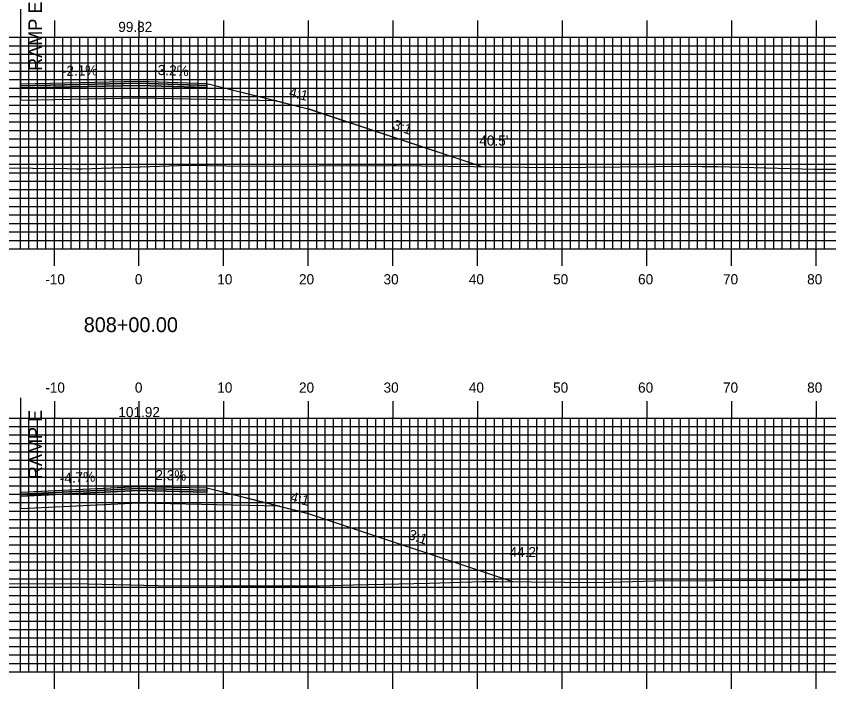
# Model space of a CAD drawing. Extents: x 1272 to 1616, y -1658 to -1438.
# Drawn here: x 1423.7 to 1519.7, y -1591.6 to -1512.1 of the extents above; entities that cross this region are included whole.
import ezdxf

# ---------------------------------------------------------------- set-up
doc = ezdxf.new("R2010")
doc.units = 0
for name, color, linetype in [('ANNOTATION', 7, 'Continuous'), ('D_Roadway_Centerline', 7, 'Continuous'), ('D_Roadway_Centerline_Text', 7, 'Continuous'), ('D_Roadway_Edge_Shoulder', 7, 'Continuous'), ('D_Roadway_Edge_TW', 7, 'Continuous'), ('D_Roadway_Pavement', 7, 'Continuous'), ('D_Roadway_SlopeLines', 7, 'Continuous'), ('D_Roadway_SubGrade', 7, 'Continuous'), ('D_Text_Standard', 7, 'Continuous'), ('H_V ANNOTATION', 7, 'Continuous'), ('MAJOR', 7, 'Continuous'), ('MINOR', 7, 'Continuous'), ('S_Roadway_Centerline', 7, 'Continuous')]:
    doc.layers.add(name, color=color, linetype=linetype)

msp = doc.modelspace()

# ---------------------------------------------------------------- linework, layer by layer
at = {"layer": 'D_Roadway_Centerline'}
for points in [[(1424.161, -1520.082), (1438.161, -1519.784), (1438.184, -1519.784), (1446.161, -1520.043), (1446.184, -1520.049), (1454.425, -1522.109), (1454.436, -1522.112), (1458.161, -1523.043), (1458.218, -1523.062), (1478.655, -1529.874)], [(1424.161, -1568.35), (1438.028, -1567.696), (1438.161, -1567.689), (1446.086, -1567.873), (1446.161, -1567.874), (1454.667, -1570.001), (1454.747, -1570.021), (1458.129, -1570.867), (1458.161, -1570.874), (1482.16, -1578.874), (1482.394, -1578.952)]]:
    msp.add_lwpolyline(points, dxfattribs=at)
at = {"layer": 'D_Roadway_Edge_Shoulder'}
for points in [[(1438.161, -1519.784), (1446.161, -1520.043), (1446.161, -1520.293), (1438.161, -1520.034)], [(1438.161, -1567.689), (1446.161, -1567.874), (1446.161, -1568.124), (1438.161, -1567.939)]]:
    msp.add_lwpolyline(points, close=True, dxfattribs=at)
at = {"layer": 'D_Roadway_Edge_TW'}
for points in [[(1424.161, -1520.082), (1438.161, -1519.784), (1438.161, -1520.034), (1424.161, -1520.332)], [(1424.161, -1568.35), (1438.161, -1567.689), (1438.161, -1567.939), (1424.161, -1568.6)]]:
    msp.add_lwpolyline(points, close=True, dxfattribs=at)
at = {"layer": 'D_Roadway_Pavement'}
for points in [[(1424.161, -1520.332), (1438.161, -1520.034), (1438.161, -1520.284), (1424.161, -1520.582)], [(1438.161, -1520.034), (1446.161, -1520.293), (1446.161, -1520.543), (1438.161, -1520.284)], [(1424.161, -1568.6), (1438.161, -1567.939), (1438.161, -1568.189), (1424.161, -1568.85)], [(1438.161, -1567.939), (1446.161, -1568.124), (1446.161, -1568.374), (1438.161, -1568.189)]]:
    msp.add_lwpolyline(points, close=True, dxfattribs=at)
for points in [[(1438.161, -1520.034), (1438.161, -1520.284)], [(1438.161, -1520.034), (1438.161, -1520.284)], [(1438.161, -1520.034), (1438.161, -1520.284)], [(1438.161, -1567.939), (1438.161, -1568.189)], [(1438.161, -1567.939), (1438.161, -1568.189)], [(1438.161, -1567.939), (1438.161, -1568.189)]]:
    msp.add_lwpolyline(points, dxfattribs=at)
at = {"layer": 'D_Roadway_SlopeLines'}
for points in [[(1446.161, -1520.043), (1458.161, -1523.043), (1478.655, -1529.874)], [(1446.161, -1567.874), (1458.161, -1570.874), (1482.394, -1578.952)], [(1446.161, -1567.874), (1458.161, -1570.874), (1482.394, -1578.952)]]:
    msp.add_lwpolyline(points, dxfattribs=at)
at = {"layer": 'D_Roadway_SubGrade'}
for p, q in [((1424.161, -1508.942), (1424.161, -1522.082)), ((1424.161, -1557.21), (1424.161, -1570.35))]:
    msp.add_line(p, q, dxfattribs=at)
for points in [[(1424.161, -1520.582), (1438.161, -1520.284), (1438.161, -1521.784), (1424.161, -1522.082)], [(1438.161, -1520.284), (1438.161, -1520.034), (1446.161, -1520.293), (1446.161, -1520.043), (1454.425, -1522.109), (1438.161, -1521.784)], [(1438.161, -1520.284), (1446.161, -1520.543), (1446.161, -1520.293), (1446.161, -1520.043), (1454.425, -1522.109), (1438.161, -1521.784)], [(1424.161, -1568.85), (1438.161, -1568.189), (1438.161, -1569.689), (1424.161, -1570.35)], [(1438.161, -1568.189), (1438.161, -1567.939), (1446.161, -1568.124), (1446.161, -1567.874), (1454.747, -1570.021), (1438.161, -1569.689)], [(1438.161, -1568.189), (1446.161, -1568.374), (1446.161, -1568.124), (1446.161, -1567.874), (1454.747, -1570.021), (1438.161, -1569.689)]]:
    msp.add_lwpolyline(points, close=True, dxfattribs=at)
at = {"layer": 'MAJOR'}
for p, q in [((1428.161, -1512.6), (1428.161, -1514.604)), ((1438.161, -1512.6), (1438.161, -1514.604)), ((1448.161, -1512.6), (1448.161, -1514.604)), ((1458.161, -1512.6), (1458.161, -1514.604)), ((1468.161, -1512.6), (1468.161, -1514.604)), ((1478.161, -1512.6), (1478.161, -1514.604)), ((1488.161, -1512.6), (1488.161, -1514.604)), ((1498.161, -1512.6), (1498.161, -1514.604)), ((1508.161, -1512.6), (1508.161, -1514.604)), ((1518.161, -1512.6), (1518.161, -1514.604)), ((1298.161, -1514.604), (1578.161, -1514.604)), ((1298.161, -1514.604), (1578.161, -1514.604)), ((1428.161, -1539.604), (1428.161, -1514.604)), ((1438.161, -1539.604), (1438.161, -1514.604)), ((1448.161, -1539.604), (1448.161, -1514.604)), ((1458.161, -1539.604), (1458.161, -1514.604)), ((1468.161, -1539.604), (1468.161, -1514.604)), ((1478.161, -1539.604), (1478.161, -1514.604)), ((1488.161, -1539.604), (1488.161, -1514.604)), ((1498.161, -1539.604), (1498.161, -1514.604)), ((1508.161, -1539.604), (1508.161, -1514.604)), ((1518.161, -1539.604), (1518.161, -1514.604)), ((1298.161, -1519.604), (1578.161, -1519.604)), ((1298.161, -1524.604), (1578.161, -1524.604)), ((1298.161, -1529.604), (1578.161, -1529.604)), ((1298.161, -1534.604), (1578.161, -1534.604)), ((1298.161, -1539.604), (1578.161, -1539.604)), ((1298.161, -1539.604), (1578.161, -1539.604)), ((1428.161, -1541.608), (1428.161, -1539.604)), ((1438.161, -1541.608), (1438.161, -1539.604)), ((1448.161, -1541.608), (1448.161, -1539.604)), ((1458.161, -1541.608), (1458.161, -1539.604)), ((1468.161, -1541.608), (1468.161, -1539.604)), ((1478.161, -1541.608), (1478.161, -1539.604)), ((1488.161, -1541.608), (1488.161, -1539.604)), ((1498.161, -1541.608), (1498.161, -1539.604)), ((1508.161, -1541.608), (1508.161, -1539.604)), ((1518.161, -1541.608), (1518.161, -1539.604)), ((1428.161, -1557.6), (1428.161, -1559.604)), ((1438.161, -1557.6), (1438.161, -1559.604)), ((1448.161, -1557.6), (1448.161, -1559.604)), ((1458.161, -1557.6), (1458.161, -1559.604)), ((1468.161, -1557.6), (1468.161, -1559.604)), ((1478.161, -1557.6), (1478.161, -1559.604)), ((1488.161, -1557.6), (1488.161, -1559.604)), ((1498.161, -1557.6), (1498.161, -1559.604)), ((1508.161, -1557.6), (1508.161, -1559.604)), ((1518.161, -1557.6), (1518.161, -1559.604)), ((1298.161, -1559.604), (1578.161, -1559.604)), ((1298.161, -1559.604), (1578.161, -1559.604)), ((1428.161, -1589.604), (1428.161, -1559.604)), ((1438.161, -1589.604), (1438.161, -1559.604)), ((1448.161, -1589.604), (1448.161, -1559.604)), ((1458.161, -1589.604), (1458.161, -1559.604)), ((1468.161, -1589.604), (1468.161, -1559.604)), ((1478.161, -1589.604), (1478.161, -1559.604)), ((1488.161, -1589.604), (1488.161, -1559.604)), ((1498.161, -1589.604), (1498.161, -1559.604)), ((1508.161, -1589.604), (1508.161, -1559.604)), ((1518.161, -1589.604), (1518.161, -1559.604)), ((1298.161, -1564.604), (1578.161, -1564.604)), ((1298.161, -1569.604), (1578.161, -1569.604)), ((1298.161, -1574.604), (1578.161, -1574.604)), ((1298.161, -1579.604), (1578.161, -1579.604)), ((1298.161, -1584.604), (1578.161, -1584.604)), ((1298.161, -1589.604), (1578.161, -1589.604)), ((1298.161, -1589.604), (1578.161, -1589.604)), ((1428.161, -1591.608), (1428.161, -1589.604)), ((1438.161, -1591.608), (1438.161, -1589.604)), ((1448.161, -1591.608), (1448.161, -1589.604)), ((1458.161, -1591.608), (1458.161, -1589.604)), ((1468.161, -1591.608), (1468.161, -1589.604)), ((1478.161, -1591.608), (1478.161, -1589.604)), ((1488.161, -1591.608), (1488.161, -1589.604)), ((1498.161, -1591.608), (1498.161, -1589.604)), ((1508.161, -1591.608), (1508.161, -1589.604)), ((1518.161, -1591.608), (1518.161, -1589.604))]:
    msp.add_line(p, q, dxfattribs=at)
at = {"layer": 'MINOR'}
for p, q in [((1424.161, -1539.604), (1424.161, -1514.604)), ((1425.161, -1539.604), (1425.161, -1514.604)), ((1426.161, -1539.604), (1426.161, -1514.604)), ((1427.161, -1539.604), (1427.161, -1514.604)), ((1429.161, -1539.604), (1429.161, -1514.604)), ((1430.161, -1539.604), (1430.161, -1514.604)), ((1431.161, -1539.604), (1431.161, -1514.604)), ((1432.161, -1539.604), (1432.161, -1514.604)), ((1433.161, -1539.604), (1433.161, -1514.604)), ((1434.161, -1539.604), (1434.161, -1514.604)), ((1435.161, -1539.604), (1435.161, -1514.604)), ((1436.161, -1539.604), (1436.161, -1514.604)), ((1437.161, -1539.604), (1437.161, -1514.604)), ((1439.161, -1539.604), (1439.161, -1514.604)), ((1440.161, -1539.604), (1440.161, -1514.604)), ((1441.161, -1539.604), (1441.161, -1514.604)), ((1442.161, -1539.604), (1442.161, -1514.604)), ((1443.161, -1539.604), (1443.161, -1514.604)), ((1444.161, -1539.604), (1444.161, -1514.604)), ((1445.161, -1539.604), (1445.161, -1514.604)), ((1446.161, -1539.604), (1446.161, -1514.604)), ((1447.161, -1539.604), (1447.161, -1514.604)), ((1449.161, -1539.604), (1449.161, -1514.604)), ((1450.161, -1539.604), (1450.161, -1514.604)), ((1451.161, -1539.604), (1451.161, -1514.604)), ((1452.161, -1539.604), (1452.161, -1514.604)), ((1453.161, -1539.604), (1453.161, -1514.604)), ((1454.161, -1539.604), (1454.161, -1514.604)), ((1455.161, -1539.604), (1455.161, -1514.604)), ((1456.161, -1539.604), (1456.161, -1514.604)), ((1457.161, -1539.604), (1457.161, -1514.604)), ((1459.161, -1539.604), (1459.161, -1514.604)), ((1460.161, -1539.604), (1460.161, -1514.604)), ((1461.161, -1539.604), (1461.161, -1514.604)), ((1462.161, -1539.604), (1462.161, -1514.604)), ((1463.161, -1539.604), (1463.161, -1514.604)), ((1464.161, -1539.604), (1464.161, -1514.604)), ((1465.161, -1539.604), (1465.161, -1514.604)), ((1466.161, -1539.604), (1466.161, -1514.604)), ((1467.161, -1539.604), (1467.161, -1514.604)), ((1469.161, -1539.604), (1469.161, -1514.604)), ((1470.161, -1539.604), (1470.161, -1514.604)), ((1471.161, -1539.604), (1471.161, -1514.604)), ((1472.161, -1539.604), (1472.161, -1514.604)), ((1473.161, -1539.604), (1473.161, -1514.604)), ((1474.161, -1539.604), (1474.161, -1514.604)), ((1475.161, -1539.604), (1475.161, -1514.604)), ((1476.161, -1539.604), (1476.161, -1514.604)), ((1477.161, -1539.604), (1477.161, -1514.604)), ((1479.161, -1539.604), (1479.161, -1514.604)), ((1480.161, -1539.604), (1480.161, -1514.604)), ((1481.161, -1539.604), (1481.161, -1514.604)), ((1482.161, -1539.604), (1482.161, -1514.604)), ((1483.161, -1539.604), (1483.161, -1514.604)), ((1484.161, -1539.604), (1484.161, -1514.604)), ((1485.161, -1539.604), (1485.161, -1514.604)), ((1486.161, -1539.604), (1486.161, -1514.604)), ((1487.161, -1539.604), (1487.161, -1514.604)), ((1489.161, -1539.604), (1489.161, -1514.604)), ((1490.161, -1539.604), (1490.161, -1514.604)), ((1491.161, -1539.604), (1491.161, -1514.604)), ((1492.161, -1539.604), (1492.161, -1514.604)), ((1493.161, -1539.604), (1493.161, -1514.604)), ((1494.161, -1539.604), (1494.161, -1514.604)), ((1495.161, -1539.604), (1495.161, -1514.604)), ((1496.161, -1539.604), (1496.161, -1514.604)), ((1497.161, -1539.604), (1497.161, -1514.604)), ((1499.161, -1539.604), (1499.161, -1514.604)), ((1500.161, -1539.604), (1500.161, -1514.604)), ((1501.161, -1539.604), (1501.161, -1514.604)), ((1502.161, -1539.604), (1502.161, -1514.604)), ((1503.161, -1539.604), (1503.161, -1514.604)), ((1504.161, -1539.604), (1504.161, -1514.604)), ((1505.161, -1539.604), (1505.161, -1514.604)), ((1506.161, -1539.604), (1506.161, -1514.604)), ((1507.161, -1539.604), (1507.161, -1514.604)), ((1509.161, -1539.604), (1509.161, -1514.604)), ((1510.161, -1539.604), (1510.161, -1514.604)), ((1511.161, -1539.604), (1511.161, -1514.604)), ((1512.161, -1539.604), (1512.161, -1514.604)), ((1513.161, -1539.604), (1513.161, -1514.604)), ((1514.161, -1539.604), (1514.161, -1514.604)), ((1515.161, -1539.604), (1515.161, -1514.604)), ((1516.161, -1539.604), (1516.161, -1514.604)), ((1517.161, -1539.604), (1517.161, -1514.604)), ((1519.161, -1539.604), (1519.161, -1514.604)), ((1298.161, -1515.604), (1578.161, -1515.604)), ((1298.161, -1516.604), (1578.161, -1516.604)), ((1298.161, -1517.604), (1578.161, -1517.604)), ((1298.161, -1518.604), (1578.161, -1518.604)), ((1298.161, -1520.604), (1578.161, -1520.604)), ((1298.161, -1521.604), (1578.161, -1521.604)), ((1298.161, -1522.604), (1578.161, -1522.604)), ((1298.161, -1523.604), (1578.161, -1523.604)), ((1298.161, -1525.604), (1578.161, -1525.604)), ((1298.161, -1526.604), (1578.161, -1526.604)), ((1298.161, -1527.604), (1578.161, -1527.604)), ((1298.161, -1528.604), (1578.161, -1528.604)), ((1298.161, -1530.604), (1578.161, -1530.604)), ((1298.161, -1531.604), (1578.161, -1531.604)), ((1298.161, -1532.604), (1578.161, -1532.604)), ((1298.161, -1533.604), (1578.161, -1533.604)), ((1298.161, -1535.604), (1578.161, -1535.604)), ((1298.161, -1536.604), (1578.161, -1536.604)), ((1298.161, -1537.604), (1578.161, -1537.604)), ((1298.161, -1538.604), (1578.161, -1538.604)), ((1424.161, -1589.604), (1424.161, -1559.604)), ((1425.161, -1589.604), (1425.161, -1559.604)), ((1426.161, -1589.604), (1426.161, -1559.604)), ((1427.161, -1589.604), (1427.161, -1559.604)), ((1429.161, -1589.604), (1429.161, -1559.604)), ((1430.161, -1589.604), (1430.161, -1559.604)), ((1431.161, -1589.604), (1431.161, -1559.604)), ((1432.161, -1589.604), (1432.161, -1559.604)), ((1433.161, -1589.604), (1433.161, -1559.604)), ((1434.161, -1589.604), (1434.161, -1559.604)), ((1435.161, -1589.604), (1435.161, -1559.604)), ((1436.161, -1589.604), (1436.161, -1559.604)), ((1437.161, -1589.604), (1437.161, -1559.604)), ((1439.161, -1589.604), (1439.161, -1559.604)), ((1440.161, -1589.604), (1440.161, -1559.604)), ((1441.161, -1589.604), (1441.161, -1559.604)), ((1442.161, -1589.604), (1442.161, -1559.604)), ((1443.161, -1589.604), (1443.161, -1559.604)), ((1444.161, -1589.604), (1444.161, -1559.604)), ((1445.161, -1589.604), (1445.161, -1559.604)), ((1446.161, -1589.604), (1446.161, -1559.604)), ((1447.161, -1589.604), (1447.161, -1559.604)), ((1449.161, -1589.604), (1449.161, -1559.604)), ((1450.161, -1589.604), (1450.161, -1559.604)), ((1451.161, -1589.604), (1451.161, -1559.604)), ((1452.161, -1589.604), (1452.161, -1559.604)), ((1453.161, -1589.604), (1453.161, -1559.604)), ((1454.161, -1589.604), (1454.161, -1559.604)), ((1455.161, -1589.604), (1455.161, -1559.604)), ((1456.161, -1589.604), (1456.161, -1559.604)), ((1457.161, -1589.604), (1457.161, -1559.604)), ((1459.161, -1589.604), (1459.161, -1559.604)), ((1460.161, -1589.604), (1460.161, -1559.604)), ((1461.161, -1589.604), (1461.161, -1559.604)), ((1462.161, -1589.604), (1462.161, -1559.604)), ((1463.161, -1589.604), (1463.161, -1559.604)), ((1464.161, -1589.604), (1464.161, -1559.604)), ((1465.161, -1589.604), (1465.161, -1559.604)), ((1466.161, -1589.604), (1466.161, -1559.604)), ((1467.161, -1589.604), (1467.161, -1559.604)), ((1469.161, -1589.604), (1469.161, -1559.604)), ((1470.161, -1589.604), (1470.161, -1559.604)), ((1471.161, -1589.604), (1471.161, -1559.604)), ((1472.161, -1589.604), (1472.161, -1559.604)), ((1473.161, -1589.604), (1473.161, -1559.604)), ((1474.161, -1589.604), (1474.161, -1559.604)), ((1475.161, -1589.604), (1475.161, -1559.604)), ((1476.161, -1589.604), (1476.161, -1559.604)), ((1477.161, -1589.604), (1477.161, -1559.604)), ((1479.161, -1589.604), (1479.161, -1559.604)), ((1480.161, -1589.604), (1480.161, -1559.604)), ((1481.161, -1589.604), (1481.161, -1559.604)), ((1482.161, -1589.604), (1482.161, -1559.604)), ((1483.161, -1589.604), (1483.161, -1559.604)), ((1484.161, -1589.604), (1484.161, -1559.604)), ((1485.161, -1589.604), (1485.161, -1559.604)), ((1486.161, -1589.604), (1486.161, -1559.604)), ((1487.161, -1589.604), (1487.161, -1559.604)), ((1489.161, -1589.604), (1489.161, -1559.604)), ((1490.161, -1589.604), (1490.161, -1559.604)), ((1491.161, -1589.604), (1491.161, -1559.604)), ((1492.161, -1589.604), (1492.161, -1559.604)), ((1493.161, -1589.604), (1493.161, -1559.604)), ((1494.161, -1589.604), (1494.161, -1559.604)), ((1495.161, -1589.604), (1495.161, -1559.604)), ((1496.161, -1589.604), (1496.161, -1559.604)), ((1497.161, -1589.604), (1497.161, -1559.604)), ((1499.161, -1589.604), (1499.161, -1559.604)), ((1500.161, -1589.604), (1500.161, -1559.604)), ((1501.161, -1589.604), (1501.161, -1559.604)), ((1502.161, -1589.604), (1502.161, -1559.604)), ((1503.161, -1589.604), (1503.161, -1559.604)), ((1504.161, -1589.604), (1504.161, -1559.604)), ((1505.161, -1589.604), (1505.161, -1559.604)), ((1506.161, -1589.604), (1506.161, -1559.604)), ((1507.161, -1589.604), (1507.161, -1559.604)), ((1509.161, -1589.604), (1509.161, -1559.604)), ((1510.161, -1589.604), (1510.161, -1559.604)), ((1511.161, -1589.604), (1511.161, -1559.604)), ((1512.161, -1589.604), (1512.161, -1559.604)), ((1513.161, -1589.604), (1513.161, -1559.604)), ((1514.161, -1589.604), (1514.161, -1559.604)), ((1515.161, -1589.604), (1515.161, -1559.604)), ((1516.161, -1589.604), (1516.161, -1559.604)), ((1517.161, -1589.604), (1517.161, -1559.604)), ((1519.161, -1589.604), (1519.161, -1559.604)), ((1298.161, -1560.604), (1578.161, -1560.604)), ((1298.161, -1561.604), (1578.161, -1561.604)), ((1298.161, -1562.604), (1578.161, -1562.604)), ((1298.161, -1563.604), (1578.161, -1563.604)), ((1298.161, -1565.604), (1578.161, -1565.604)), ((1298.161, -1566.604), (1578.161, -1566.604)), ((1298.161, -1567.604), (1578.161, -1567.604)), ((1298.161, -1568.604), (1578.161, -1568.604)), ((1298.161, -1570.604), (1578.161, -1570.604)), ((1298.161, -1571.604), (1578.161, -1571.604)), ((1298.161, -1572.604), (1578.161, -1572.604)), ((1298.161, -1573.604), (1578.161, -1573.604)), ((1298.161, -1575.604), (1578.161, -1575.604)), ((1298.161, -1576.604), (1578.161, -1576.604)), ((1298.161, -1577.604), (1578.161, -1577.604)), ((1298.161, -1578.604), (1578.161, -1578.604)), ((1298.161, -1580.604), (1578.161, -1580.604)), ((1298.161, -1581.604), (1578.161, -1581.604)), ((1298.161, -1582.604), (1578.161, -1582.604)), ((1298.161, -1583.604), (1578.161, -1583.604)), ((1298.161, -1585.604), (1578.161, -1585.604)), ((1298.161, -1586.604), (1578.161, -1586.604)), ((1298.161, -1587.604), (1578.161, -1587.604)), ((1298.161, -1588.604), (1578.161, -1588.604))]:
    msp.add_line(p, q, dxfattribs=at)
at = {"layer": 'S_Roadway_Centerline'}
for points in [[(1413.396, -1529.961), (1429.638, -1530.096), (1430.822, -1530.149), (1431.448, -1530.135), (1444.005, -1529.703), (1450.781, -1529.82), (1468.074, -1529.741), (1468.298, -1529.743), (1468.536, -1529.743), (1486.823, -1529.98), (1503.187, -1529.846), (1504.706, -1529.859), (1506.515, -1529.882), (1517.922, -1530.201), (1523.796, -1530.205), (1530.869, -1530.037), (1541.617, -1529.637), (1542.342, -1529.609), (1559.166, -1529.257), (1575.461, -1529.304), (1577.547, -1529.348), (1578.161, -1529.362)], [(1417.658, -1579.206), (1430.508, -1579.166), (1440.39, -1579.411), (1447.767, -1579.456), (1459.45, -1579.436), (1463.488, -1579.342), (1472.434, -1579.118), (1478.76, -1578.945), (1480.566, -1578.936), (1492.453, -1579.044), (1499.139, -1578.843), (1513.318, -1578.791), (1515.997, -1578.759), (1517.24, -1578.738), (1522.793, -1578.712), (1531.635, -1578.65), (1533.45, -1578.669), (1544.236, -1578.641), (1551.493, -1578.592), (1564.482, -1578.691), (1568.385, -1578.804), (1570.235, -1578.783), (1577.631, -1579.099), (1578.161, -1579.116)]]:
    msp.add_lwpolyline(points, dxfattribs=at)

# ---------------------------------------------------------------- texts
at = {"layer": 'ANNOTATION'}
for s, height, rotation, p in [('RAMP E', 1.6, 90, (1426.692, -1518.573)), ('-2.1%', 1.2, 1.22083, (1429.064, -1519.177)), ('-3.2%', 1.2, 358.14522, (1439.83, -1519.037)), ('4:1', 1.2, 345.96431, (1455.804, -1521.592)), ('3:1', 1.2, 341.56532, (1468.04, -1525.428)), ('RAMP E', 1.6, 90, (1426.692, -1566.841)), ('2.3%', 1.2, 358.67387, (1440.083, -1566.933)), ('-4.7%', 1.2, 2.70067, (1428.832, -1567.327)), ('4:1', 1.2, 345.96379, (1455.944, -1569.459)), ('3:1', 1.2, 341.56522, (1469.881, -1573.873))]:
    msp.add_text(s, height=height, rotation=rotation, dxfattribs=at).set_placement(p)
at = {"layer": 'D_Roadway_Centerline_Text'}
for s, p in [('99.82', (1435.715, -1513.972)), ('101.92', (1435.726, -1559.5))]:
    msp.add_text(s, height=1.2, dxfattribs=at).set_placement(p)
at = {"layer": 'D_Text_Standard'}
for s, p in [("40.5'", (1478.375, -1527.404)), ("44.2'", (1481.947, -1576.053))]:
    msp.add_text(s, height=1.2, dxfattribs=at).set_placement(p)
at = {"layer": 'H_V ANNOTATION'}
for s, height, p in [('-10', 1.2, (1427.09, -1543.804)), ('0', 1.2, (1437.679, -1543.804)), ('10', 1.2, (1447.411, -1543.804)), ('20', 1.2, (1457.068, -1543.804)), ('30', 1.2, (1467.058, -1543.804)), ('40', 1.2, (1477.133, -1543.804)), ('50', 1.2, (1487.09, -1543.804)), ('60', 1.2, (1497.133, -1543.804)), ('70', 1.2, (1507.165, -1543.804)), ('80', 1.2, (1517.111, -1543.804)), ('808+00.00', 1.75, (1431.637, -1549.448)), ('-10', 1.2, (1427.09, -1556.604)), ('0', 1.2, (1437.679, -1556.604)), ('10', 1.2, (1447.411, -1556.604)), ('20', 1.2, (1457.068, -1556.604)), ('30', 1.2, (1467.058, -1556.604)), ('40', 1.2, (1477.133, -1556.604)), ('50', 1.2, (1487.09, -1556.604)), ('60', 1.2, (1497.133, -1556.604)), ('70', 1.2, (1507.165, -1556.604)), ('80', 1.2, (1517.111, -1556.604))]:
    msp.add_text(s, height=height, dxfattribs=at).set_placement(p)

doc.saveas('drawing.dxf')
